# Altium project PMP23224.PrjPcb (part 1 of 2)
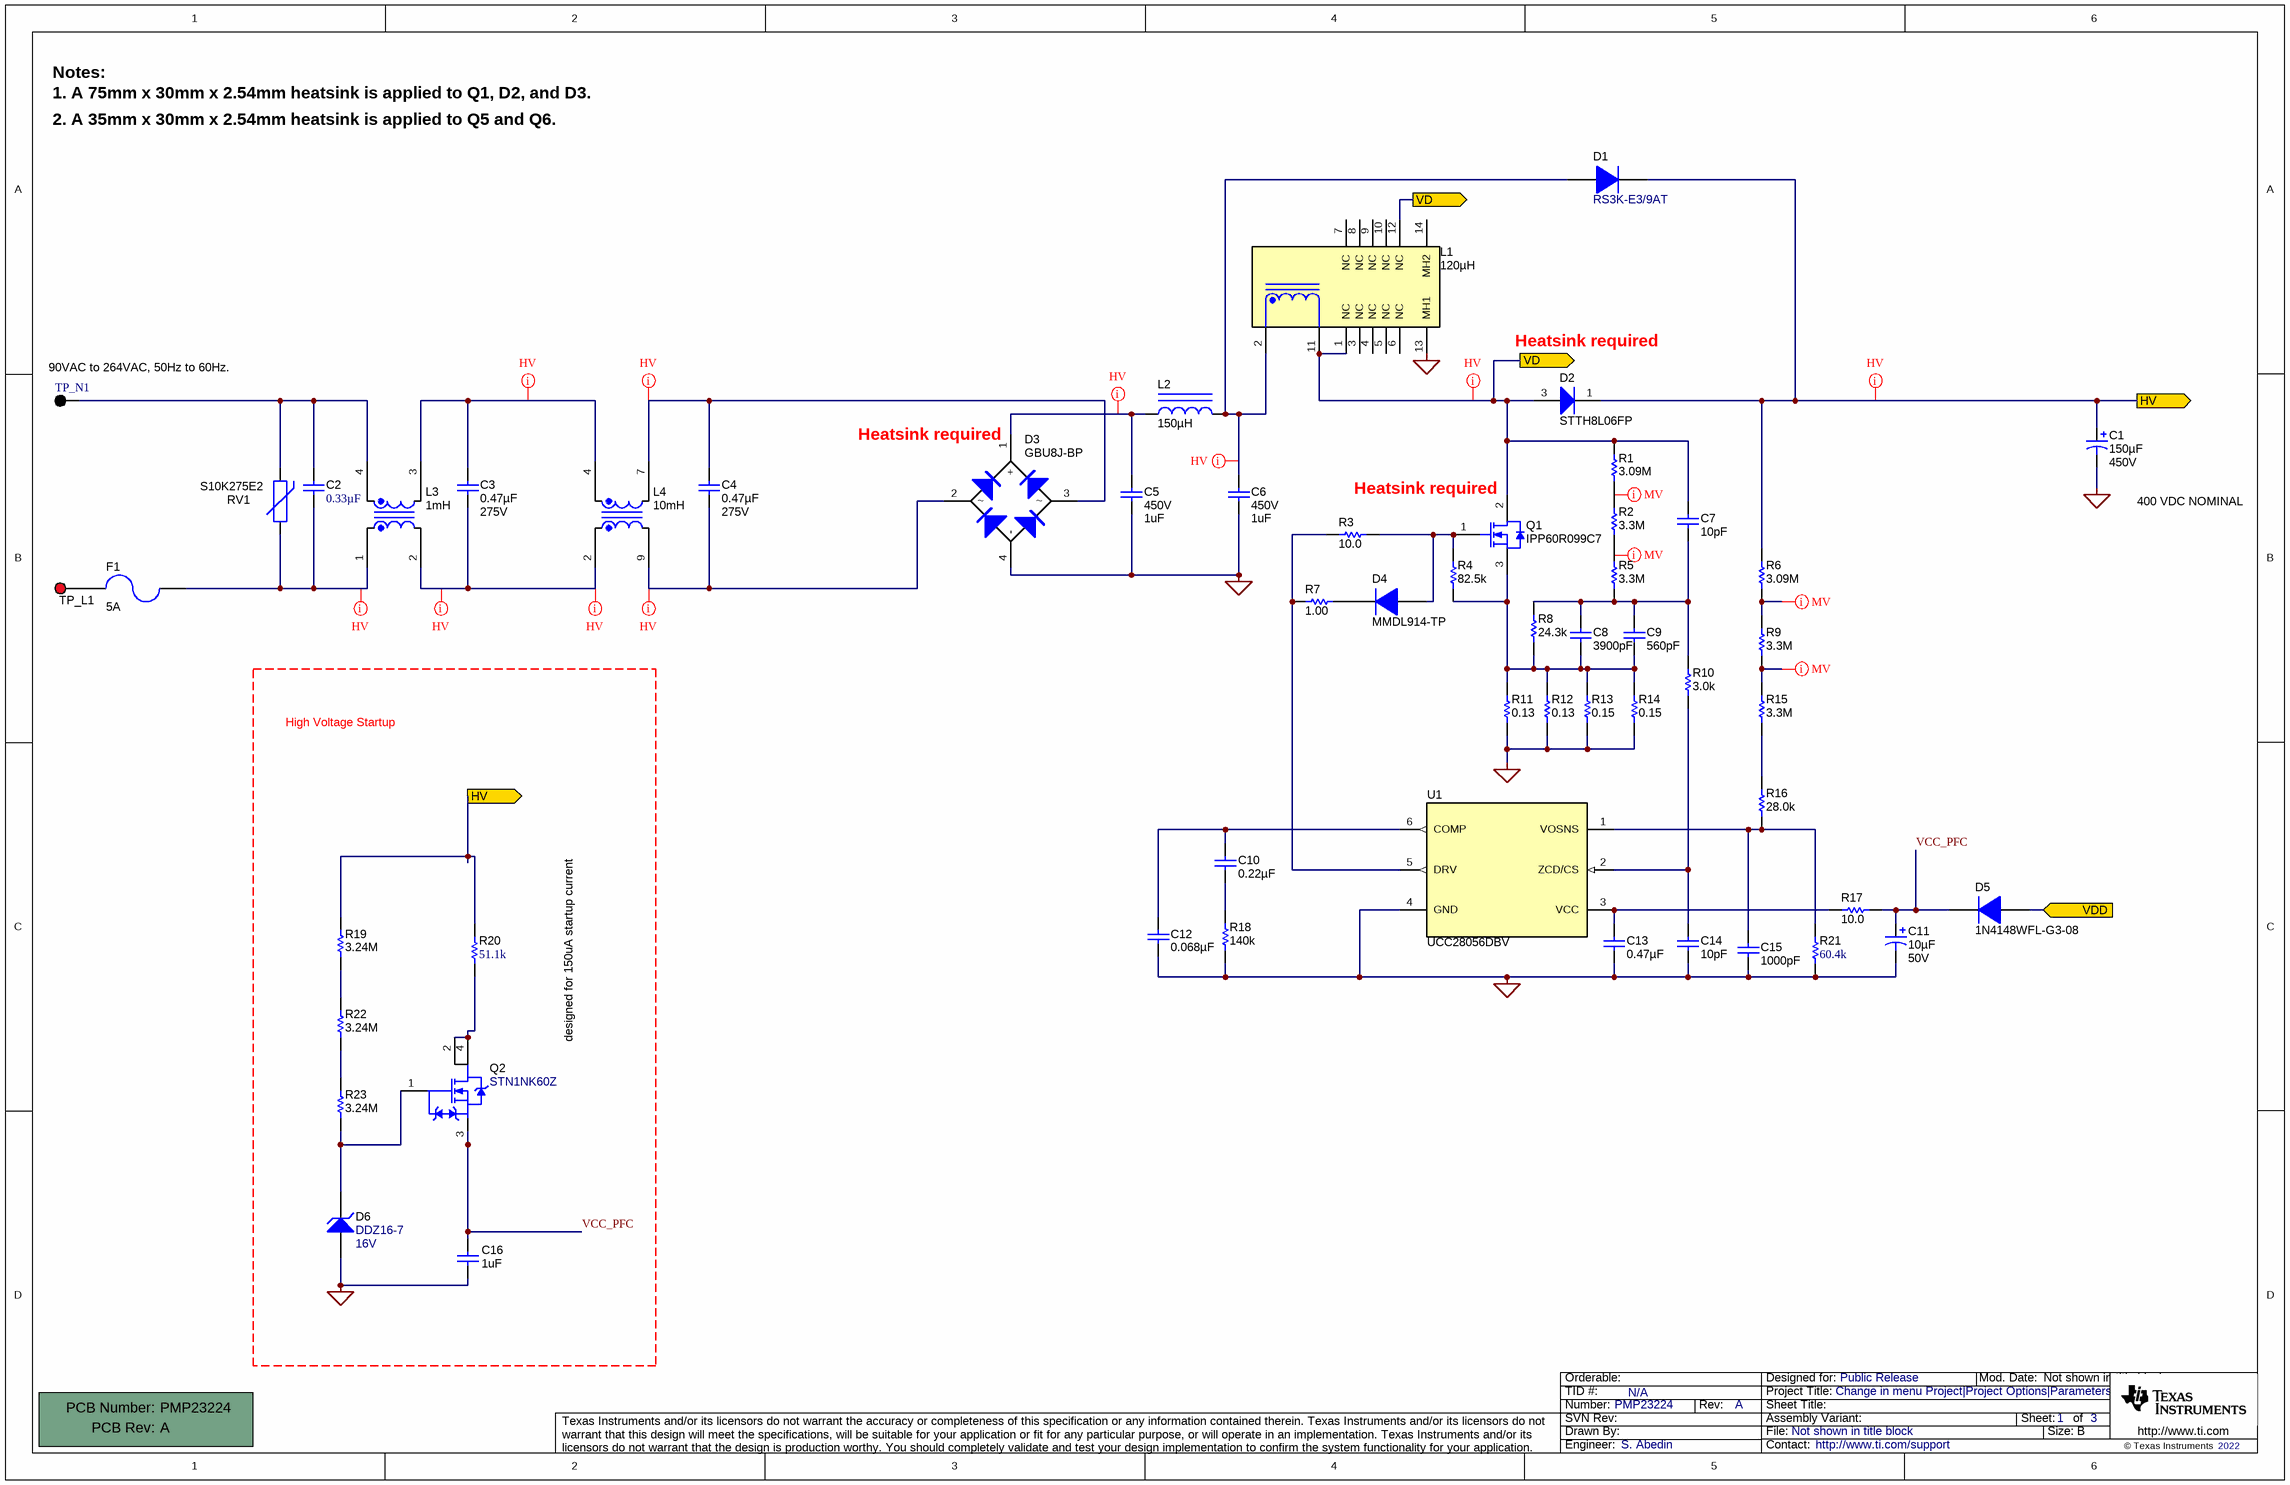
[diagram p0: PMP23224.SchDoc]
CopyrightYear: 2022; PCB_Layout: S. Abedin; PCB_Rev: A; PRJ_Customer: Public Release; PRJ_Engineer: S. Abedin; PRJ_Number: PMP23224; PRJ_Title: Change in menu Project|Project Options|Parameters; SCH_Rev: A; TechSupport: http://www.ti.com/support; TID: N/A
3 sheets, 191 parts. Net scope: flat (ports and power ports of the same name join across sheets).
Board file: PMP23224.PcbDoc
Sheets:
  PMP23224.SchDoc
  PMP23224_BlankSheet.SchDoc
  PMP23224_ACF_secondary.SchDoc

## Sheet PMP23224.SchDoc
size 431 x 279 mm; Date: Not shown in title block; ApprovedBy: Not shown in title block; CheckedBy: Not shown in title block; Author: Not shown in title block; CompanyName: Not shown in title block; Engineer: Not shown in title block; Organization: Not shown in title block; Address1: Not shown in title block; Address2: Not shown in title block; Address3: Not shown in title block; Address4: Not shown in title block; DocumentNumber: 1; Revision: Use project parameter SCH_Rev; SheetNumber: 1; SheetTotal: 3; PageSetup: Record=PageOptions¦CenterHorizontal=True¦CenterVertical=True¦PrintScale=1.00¦XCorrection=1.00¦YCorrection=1.00¦PrintKind=0¦BorderSize=5000000¦LeftOffset=0¦BottomOffset=0¦Orientation=2¦PaperLength=1000¦PaperWidth=1000¦Scale=100¦PaperSource=15¦PrintQuality=600¦MediaType=1¦DitherType=10¦PaperKind=Letter¦PrintScaleMode=1

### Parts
!PCB1  Printed Circuit Board  (value not drawn)  (mechanical)
C1  ValueDisplayed: 150µF  Value2: 450V  [SMQ_2540x2500]  (hidden comment: 450MXK150MEFCSN25X25)
C2  ValueDisplayed: 0.33µF  [WCAP-FTX2_1500x850]  (hidden comment: 890324024003)
C3  ValueDisplayed: 0.47µF  VAC_X: 275V  [WCAP-FTX2_1500x1000x1600]  (hidden comment: 890324024005)
C4  ValueDisplayed: 0.47µF  VAC_X: 275V  [WCAP-FTX2_1500x1000x1600]  (hidden comment: 890324024005)
C5  VDC_V: 450V  ValueDisplayed: 1uF  [MPK_1800x950]  (hidden comment: 450MPK105J)
C6  VDC_V: 450V  ValueDisplayed: 1uF  [MPK_1800x950]  (hidden comment: 450MPK105J)
C7  ValueDisplayed: 10pF  [1206]  (hidden comment: VJ1206A100JXGAT5Z)
C8  ValueDisplayed: 3900pF  [0603]  (hidden comment: GRM188R71E392KA01D)
C9  ValueDisplayed: 560pF  [0603]  (hidden comment: 06035A561JAT2A)
C10  ValueDisplayed: 0.22µF  [0603]  (hidden comment: 885012206048)
C11  ValueDisplayed: 10µF  Value2: 50V  [NHG_500x1100]  (hidden comment: ECA-1HHG100)
C12  ValueDisplayed: 0.068µF  [0603]  (hidden comment: C1608X5R1H683K080AA)
C13  ValueDisplayed: 0.47µF  [1206_180]  (hidden comment: CGA5L2X7R1H474K160AA)
C14  ValueDisplayed: 10pF  [0603]  (hidden comment: 0603ZC100KAT2A)
C15  ValueDisplayed: 1000pF  [0603]  (hidden comment: 06031C102KAT2A)
C16  ValueDisplayed: 1uF  [0805_HV1]  (hidden comment: C0805C105K3RACTU)
D1  RS3K-E3/9AT  [SMC]
D2  STTH8L06FP  [TO-220AC]
D3  GBU8J-BP  [GBU]
D4  MMDL914-TP  [SOD-323]
D5  1N4148WFL-G3-08  [SOD-123FL]
D6  DDZ16-7  value 16V  [SOD-123]
F1  Irating_A: 5A  [FUSE_372]  (hidden comment: 37215000001)
L1  ValueDisplayed: 120µH  [750317259]  (hidden comment: 750317259)
L2  ValueDisplayed: 150µH  [IND_7447020]  (hidden comment: 7447018)
L3  ValueDisplayed: 1mH  [IND_WE-CMB-S]  (hidden comment: 744822301)
L4  ValueDisplayed: 10mH  [IND_WE-CMB_L]  (hidden comment: 744824310)
Q1  IPP60R099C7  [TO-220AB]
Q2  STN1NK60Z  [SOT-223]
R1  ValueDisplayed: 3.09M  [1206]  (hidden comment: CRCW12063M09FKEA)
R2  ValueDisplayed: 3.3M  [1206]  (hidden comment: CRCW12063M30JNEA)
R3  ValueDisplayed: 10.0  [0603]  (hidden comment: CRCW060310R0FKEA)
R4  ValueDisplayed: 82.5k  [0603]  (hidden comment: CRCW060382K5FKEA)
R5  ValueDisplayed: 3.3M  [1206]  (hidden comment: CRCW12063M30JNEA)
R6  ValueDisplayed: 3.09M  [1206]  (hidden comment: CRCW12063M09FKEA)
R7  ValueDisplayed: 1.00  [0603]  (hidden comment: CRCW06031R00FKEA)
R8  ValueDisplayed: 24.3k  [0603]  (hidden comment: CRCW060324K3FKEA)
R9  ValueDisplayed: 3.3M  [1206]  (hidden comment: CRCW12063M30JNEA)
R10  ValueDisplayed: 3.0k  [0603]  (hidden comment: CRCW06033K00JNEA)
R11  ValueDisplayed: 0.13  [1206]  (hidden comment: CSR1206FTR130)
R12  ValueDisplayed: 0.13  [1206]  (hidden comment: CSR1206FTR130)
R13  ValueDisplayed: 0.15  [1206]  (hidden comment: ERJ-8BSFR15V)
R14  ValueDisplayed: 0.15  [1206]  (hidden comment: ERJ-8BSFR15V)
R15  ValueDisplayed: 3.3M  [1206]  (hidden comment: CRCW12063M30JNEA)
R16  ValueDisplayed: 28.0k  [0603]  (hidden comment: CRCW060328K0FKEA)
R17  ValueDisplayed: 10.0  [0805_HV]  (hidden comment: CRCW080510R0FKEA)
R18  ValueDisplayed: 140k  [0603]  (hidden comment: CRCW0603140KFKEA)
R19  ValueDisplayed: 3.24M  [1206]  (hidden comment: CRCW12063M24FKEA)
R20  ValueDisplayed: 51.1k  [1206]  (hidden comment: CRCW120651K1FKEA)
R21  ValueDisplayed: 60.4k  [0603]  (hidden comment: CRCW060360K4FKEA)
R22  ValueDisplayed: 3.24M  [1206]  (hidden comment: CRCW12063M24FKEA)
R23  ValueDisplayed: 3.24M  [1206]  (hidden comment: CRCW12063M24FKEA)
RV1  S10K275E2  [VAR_S10K275E2]
TP_L1  5010  [Keystone5010]  (value not drawn)
TP_N1  TP_N100  [Keystone5011]  (value not drawn)
U1  UCC28056DBV  [DBV0006A_N]

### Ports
HV (out), VD (out), VDD (in)

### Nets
GND: C1.2(-) C5.2 C6.2 C11.2(-) C12.2 C13.2 C14.2 C15.2 C16.2 D3.4(-) D6.2(A) L1.13(MH1) R11.1 R12.1 R13.1 R14.1 R18.1 R21.1 U1.4(GND)
HV: C1.1(+) D1.1(K) D2.1(K) R6.2 R19.2 R20.2 ; port HV
VCC_PFC: C11.1(+) C16.1 D5.1(K) Q2.3(S) R17.2
VD: C7.1 D2.3(A) L1.1(NC) L1.11 L1.12(NC) Q1.2(D) R1.2 ; port VD
VDD: D5.2(A) ; port VDD
NetC2_1: C2.1 L3.4 RV1.2 TP_N1.1
NetC2_2: C2.2 F1.2 L3.1 RV1.1
NetC3_1: C3.1 L3.3 L4.4
NetC3_2: C3.2 L3.2 L4.2
NetC4_1: C4.1 D3.3 L4.7
NetC4_2: C4.2 D3.2 L4.9
NetC5_1: C5.1 D3.1(+) L2.1
NetC6_1: C6.1 D1.2(A) L1.2 L2.2
NetC7_2: C7.2 C8.1 C9.1 R5.1 R8.2 R10.1
NetC8_2: C8.2 C9.2 Q1.3(S) R4.1 R8.1 R11.2 R12.2 R13.2 R14.2
NetC10_1: C10.1 C12.1 U1.6(COMP)
NetC10_2: C10.2 R18.2
NetC13_1: C13.1 R17.1 U1.3(VCC)
NetC14_1: C14.1 R10.2 U1.2(ZCD/CS)
NetC15_1: C15.1 R16.1 R21.2 U1.1(VOSNS)
NetD4_1: D4.1(K) R7.2
NetD4_2: D4.2(A) Q1.1(G) R3.2 R4.2
NetD6_1: D6.1(K) Q2.1(G) R23.1
NetF1_1: F1.1 TP_L1.1
NetQ2_2: Q2.2(D) Q2.4(D) R20.1
NetR1_1: R1.1 R2.2
NetR2_1: R2.1 R5.2
NetR3_1: R3.1 R7.1 U1.5(DRV)
NetR6_1: R6.1 R9.2
NetR9_1: R9.1 R15.2
NetR15_1: R15.1 R16.2
NetR19_1: R19.1 R22.2
NetR22_1: R22.1 R23.2

Not connected (* = marked no-connect by the designer): L1 3(NC) 4(NC) 5(NC) 6(NC) 7(NC) 8(NC) 9(NC) 10(NC) 14(MH2)

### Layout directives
net class HV: HV, NetC2_2, NetC3_1, NetC3_2, NetC4_1, NetC4_2, NetC5_1, NetC6_1, VD
net class MV: (no net found under the mark), NetR1_1, NetR6_1, NetR9_1

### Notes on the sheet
- Notes:
- 1. A 75mm x 30mm x 2.54mm heatsink is applied to Q1, D2, and D3.
- 2. A 35mm x 30mm x 2.54mm heatsink is applied to Q5 and Q6.
- (near TP_N1) 90VAC to 264VAC, 50Hz to 60Hz.
- (near D2) Heatsink required
- (near D3) Heatsink required
- Heatsink required
- 400 VDC NOMINAL
- High Voltage Startup
- designed for 150uA startup current

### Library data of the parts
!PCB1 = PCB: Manufacturer: Any; PartNumber: PMP23224; SymbolCreator: a0412235
C1 = ESMQ451VSN151MQ25S: CAP, AL, 150 µF, 450 V, +/- 20%, TH; Manufacturer: Rubycon; Polarized: Y; CompType: Capacitor; Value: 150uF; U/M: EA; Cap_F: 0.00015; Tolerance_%: 20; VDC_V: 450; IRMS_A: 1.19; TaMin_C: -25; TaMax_C: 85; Cap_Case: 25.4x25mm; SizeAreaWB_mm2: 750.76; SizeArea_mm2: 645.16; SizeX_mm: 25.4; SizeZ_mm: 27; AEC Category: Q200; AEC Qualified: N
C2 = CMP-0084596-1: CAP, Film, 0.33 µF, X2 275 VAC, +/- 10%, TH; Manufacturer: Wurth Elektronik; Cap_Case: 15x8.5mm; SizeAreaWB_mm2: 178.5; AEC Qualified: N; SizeX_mm: 15; Cap_F: 330nF; SizeY_mm: 8.5; VAC_X: 275; TaMin_C: -40°C; SizeZ_mm: 14.5; SizeArea_mm2: 127.5; Value: 0.33uF; TaMax_C: 105°C; AEC Category: Q200
C3 C4 = 890324024005: CAP, Film, 0.47 µF, X2 275 VAC, +/- 10%, TH; Manufacturer: Wurth Elektronik; Polarized: N; CompType: Capacitor; Value: 0.47uF; U/M: EA; Cap_F: 0.00000047; Tolerance_%: 10; TaMin_C: -40; TaMax_C: 105; Cap_Case: 15x10x16mm; SizeAreaWB_mm2: 204; SizeArea_mm2: 150; SizeX_mm: 15; SizeZ_mm: 16.5; AEC Category: Q200; Green_Lifecycle: Not Set; Green_REACh: Incomplete
C5 C6 = CMP-0012307-3: CAP, Film, 1 uF, 450 V, +/- 5%, TH; Manufacturer: Rubycon; TaMin_C: -40°C; Polarized: N; Value1: Unknown; Value: 1uF; TaMax_C: 105°C; Cap_Case: 18x9.5mm; CompType: Capacitor; Cap_F: 1µF; AEC Category: Q200
C7 = VJ1206A100JXGAT5Z: CAP, CERM, 10 pF, 1000 V,+/- 5%, C0G/NP0, 1206; Manufacturer: Vishay-Vitramon; Polarized: N; CompType: Capacitor; Value: 10pF; U/M: EA; Cap_F: 0.00000000001; Tolerance_%: 5; VDC_V: 1000; Value2: 1000V; TaMin_C: -55; TaMax_C: 125; SizeArea_mm2: 5.12; SizeAreaWB_mm2: 10.92; SizeX_mm: 3.2; SizeY_mm: 1.6; SizeZ_mm: 1.35; AEC Category: Q200
C8 = GRM188R71E392KA01D: CAP, CERM, 3900 pF, 25 V,+/- 10%, X7R, 0603; Manufacturer: MuRata; Polarized: N; CompType: Capacitor; Value: 3900pF; U/M: EA; Cap_F: 0.0000000039; Tolerance_%: 10; VDC_V: 25; Value2: 25V; TaMin_C: -55; TaMax_C: 125; SizeArea_mm2: 1.28; SizeAreaWB_mm2: 4.68; SizeX_mm: 1.6; SizeY_mm: 0.8; SizeZ_mm: 1; AEC Category: Q200; Green_Lifecycle: Active; Green_REACh: Passed
C9 = 06035A561JAT2A: CAP, CERM, 560 pF, 50 V,+/- 5%, C0G/NP0, 0603; Manufacturer: AVX; Polarized: N; CompType: Capacitor; Value: 560pF; U/M: EA; Cap_F: 0.00000000056; Tolerance_%: 5; ESR_ohm: 0.059; Value1: 0.059 ohm; VDC_V: 50; Value2: 50V; TaMin_C: -55; TaMax_C: 125; SizeArea_mm2: 1.28; SizeAreaWB_mm2: 4.68; SizeX_mm: 1.6; SizeY_mm: 0.8; SizeZ_mm: 1; AEC Category: Q200; Green_Lifecycle: Active; Green_REACh: Passed
C10 = 885012206048: CAP, CERM, 0.22 µF, 16 V,+/- 10%, X7R, 0603; Manufacturer: Wurth Elektronik; Polarized: N; CompType: Capacitor; Value: 0.22uF; U/M: EA; Cap_F: 0.00000022; Tolerance_%: 10; VDC_V: 16; Value2: 16V; TaMin_C: -55; TaMax_C: 125; SizeArea_mm2: 1.28; SizeAreaWB_mm2: 4.68; SizeX_mm: 1.6; SizeY_mm: 0.8; SizeZ_mm: 1; AEC Category: Q200
C11 = ECA-1HHG100: CAP, AL, 10 µF, 50 V, +/- 20%, TH; Manufacturer: Panasonic; Polarized: Y; CompType: Capacitor; Value: 10uF; U/M: EA; Cap_F: 0.00001; Tolerance_%: 20; VDC_V: 50; IRMS_A: 0.039; TaMin_C: -55; TaMax_C: 105; Cap_Case: 5x11mm; SizeAreaWB_mm2: 49; SizeArea_mm2: 25; SizeX_mm: 5; SizeZ_mm: 12; AEC Category: Q200; AEC Qualified: N
C12 = C1608X5R1H683K080AA: CAP, CERM, 0.068 µF, 50 V,+/- 10%, X5R, 0603; Manufacturer: TDK; Polarized: N; CompType: Capacitor; Value: 0.068uF; U/M: EA; Cap_F: 0.000000068; Tolerance_%: 10; ESR_ohm: 0.035979; Value1: 0.035979 ohm; VDC_V: 50; Value2: 50V; IRMS_A: 0.886483; TaMin_C: -55; TaMax_C: 85; SizeArea_mm2: 1.28; SizeAreaWB_mm2: 4.68; SizeX_mm: 1.6; SizeY_mm: 0.8; SizeZ_mm: 1; AEC Category: Q200; Green_Lifecycle: NRND; Green_REACh: Passed
C13 = CGA5L2X7R1H474K160AA: CAP, CERM, 0.47 µF, 50 V,+/- 10%, X7R, AEC-Q200 Grade 1, 1206; Manufacturer: TDK; Polarized: N; CompType: Capacitor; Value: 0.47uF; U/M: EA; Cap_F: 0.00000047; Tolerance_%: 10; ESR_ohm: 0.009426; Value1: 0.009426 ohm; VDC_V: 50; Value2: 50V; IRMS_A: 2.37046; TaMin_C: -55; TaMax_C: 125; Cap_Case: 1206; SizeArea_mm2: 5.12; SizeAreaWB_mm2: 10.92; SizeX_mm: 3.2; SizeY_mm: 1.6; SizeZ_mm: 1.8; AEC Category: Q200; AEC Qualified: Y; AEC Grade: 1
C14 = 0603ZC100KAT2A: CAP, CERM, 10 pF, 10 V,+/- 10%, X7R, 0603; Manufacturer: AVX; Polarized: N; CompType: Capacitor; Value: 10pF; U/M: EA; Cap_F: 0.00000000001; Tolerance_%: 10; Value1: Unknown; Value2: 10V; TaMin_C: -55; TaMax_C: 125; SizeArea_mm2: 1.28; SizeAreaWB_mm2: 4.68; SizeX_mm: 1.6; SizeY_mm: 0.8; SizeZ_mm: 1; AEC Category: Q200
C15 = 06031C102KAT2A: CAP, CERM, 1000 pF, 100 V,+/- 10%, X7R, 0603; Manufacturer: AVX; Polarized: N; CompType: Capacitor; Value: 1000pF; U/M: EA; Cap_F: 0.000000001; Tolerance_%: 10; ESR_ohm: 0.276; Value1: 0.276 ohm; VDC_V: 100; Value2: 100V; TaMin_C: -55; TaMax_C: 125; SizeArea_mm2: 1.28; SizeAreaWB_mm2: 4.68; SizeX_mm: 1.6; SizeY_mm: 0.8; SizeZ_mm: 1; AEC Category: Q200; Green_Lifecycle: Active; Green_REACh: Passed
C16 = CMP-0007728-2: CAP, CERM, 1 uF, 25 V, +/- 10%, X7R, 0805; Manufacturer: Kemet; Polarized: N; Value: 1uF; U/M: EA; Cap_F: 1µF; Value1: Unknown; VDC_V: 25V; TaMin_C: -55°C; TaMax_C: 125°C; Cap_Case: 0805; SizeArea_mm2: 2.5; SizeAreaWB_mm2: 6.75; SizeX_mm: 2; SizeY_mm: 1.25; SizeZ_mm: 1.45; AEC Category: Q200
D1 = CMP-0076883-2: Diode, Switching, 800 V, 3 A, SMC; Manufacturer: Vishay-Semiconductor; Vf_V: 1.3V; Value: 800V; Value1: 3A; TJmax_C: 150°C; RJC_CperW: 50.0; SizeAreaWB_mm2: 83.2686; SizeArea_mm2: 50.5686; SizeX_mm: 8.13; SizeY_mm: 6.22; SizeZ_mm: 2.6; AEC Category: Q101; Green_Lifecycle: Not Set; Green_REACh: Incomplete
D2 = STTH506DTI: DIODE GEN PURP 600V 8A TO220FP; Manufacturer: STMicroelectronics; SymbolCreator: a0412235; U/M: EA; Io_A: 5; Vr_V: 600; TJmax_C: 150; RJC_CperW: 3; Type: Ultrafast; SizeAreaWB_mm2: 78.975; SizeArea_mm2: 45.675; SizeX_mm: 10.15; SizeY_mm: 4.5; SizeZ_mm: 23; AEC Category: Q101; AEC Qualified: N; Green_Lifecycle: Not Set; Green_REACh: Incomplete
D3 = CMP-0029222-2: Diode, Switching-Bridge, 420 V, 8 A, TH; Manufacturer: Micro Commercial Components; Io_A: 8A; Green_Lifecycle: Not Set; SizeAreaWB_mm2: 130.5915; Vr_V: 420V; Green_REACh: Incomplete; TJmax_C: 175°C; U/M: EA; Value: 420V; SizeZ_mm: 21.55; SizeX_mm: 22.05; SizeY_mm: 3.43; Vf_V: 1V; SizeArea_mm2: 75.6315; AEC Category: Q101
D4 = MMDL914-TP: Diode, Switching, 100 V, 0.2 A, SOD-323; Manufacturer: Micro Commercial Components; U/M: EA; Vf_V: 1; Value: 100V; Value1: 0.2A; Value2: 1V; Io_A: 0.2; Vr_V: 100; TJmax_C: 150; SizeAreaWB_mm2: 8.695; SizeArea_mm2: 3.645; SizeX_mm: 2.7; SizeY_mm: 1.35; AEC Category: Q101
D5 = 1N4148WFL-G3-08: Diode, Switching, 100 V, 0.15 A, SOD-123FL; Manufacturer: Vishay-Semiconductor; U/M: EA; Vf_V: 1.2; Value: 100V; Value1: 0.15A; Value2: 1.2V; Io_A: 0.15; Vr_V: 100; TJmax_C: 150; SizeAreaWB_mm2: 12.19; SizeArea_mm2: 5.94; SizeX_mm: 3.6; SizeY_mm: 1.65; SizeZ_mm: 0.98; AEC Category: Q101; Green_Lifecycle: Not Set; Green_REACh: Incomplete
D6 = CMP-0085137-1: Diode, Zener, 16 V, 500 mW, SOD-123; Manufacturer: Diodes Inc.; AEC Category: Q101; SizeY_mm: 1.7; SizeX_mm: 3.85; Power_W: 500mW; SizeZ_mm: 1.35; SizeArea_mm2: 6.545; RJA_CperW: 425; AEC Qualified: N; SizeAreaWB_mm2: 13.095; Value1: 0.5W
F1 = 37215000001: Fuse, 5 A, 250VAC/VDC, TH; Manufacturer: Littelfuse; VDC_V: 250; MeltingTyp: 94
L1 = CMP-0078769-1: Inductor, 120 µH, 4 A, 0.055 ohm, TH; Manufacturer: Wurth Elektronik; SizeAreaWB_mm2: 1139.0625; SizeArea_mm2: 1008.0625; AEC Qualified: N; AEC Category: Q200; Value: 120uH; SizeZ_mm: 24.64; Imax_A: 4A; SizeY_mm: 31.75; Isat: 4A @ 20% inductance drop; DCR_ohm: 0.055
L2 = 7447020: 150µH Unshielded Toroidal Inductor 2A 80 mOhm Max Radial; Manufacturer: Wurth Elektronik; Ind_H: 100.0E-6; Imax_A: 1; Irms: 2.5A @ 40C rise; DCR_ohm: 0.16; Value1: 0.16 ohm; Material: Powdered Iron; SizeAreaWB_mm2: 169.1; SizeArea_mm2: 118.5; SizeX_mm: 7.5; SizeY_mm: 15.8; AEC Category: Q200
L3 = 744822301: Coupled inductor, 1 mH, 3 A, 0.035 ohm, TH; Manufacturer: Wurth Elektronik; SymbolCreator: a0412235; Value: 1mH; Ind_H: 1.0E-3; DCR_ohm: 0.035; AEC Category: Q200
L4 = 744824310: Coupled inductor, 10 mH, 3 A, 0.105 ohm, TH; Manufacturer: Wurth Elektronik; SymbolCreator: a0799628; Value: 10mH; Ind_H: 10.0E-3; DCR_ohm: 0.105; AEC Category: Q200
Q1 = IPP60R099C7XKSA1: MOSFET, N-CH, 600 V, 22 A, TO-220AB; Manufacturer: Infineon Technologies; Alternate Manufacturer: None; U/M: EA; ChType: N; Value: 600V; VdsMax_V: 600; Value1: ? ohm; Value2: 42 nC; QgTyp_nC: 42; Vgs_V: 30; IdsMax_A: 22; SizeAreaWB_mm2: 79.3; SizeArea_mm2: 45.9; SizeX_mm: 10.2; SizeY_mm: 4.5; SizeZ_mm: 19.4; AEC Category: Q101
Q2 = CMP-0001204-2: MOSFET, N-CH, 600 V, 0.3 A, SOT-223; Manufacturer: STMicroelectronics; Alternate Manufacturer: None; U/M: EA; ChType: N; Value: 600V; Value2: 4.9 nC; QgTyp_nC: 4.9; Vgs_V: 30V; IdsMax_A: 300mA; SizeAreaWB_mm2: 76.5; SizeArea_mm2: 45.5; SizeX_mm: 6.5; SizeY_mm: 7; SizeZ_mm: 1.6; AEC Category: Q101; AccessRights: 2147483647; ContentType: Component; Folder: Unified Components\Transistors\MOSFET\N-Channel\VDS 200 V+\; RevisionId: 1
R1 R6 = CRCW12063M09FKEA: RES, 3.09 M, 1%, 0.25 W, 1206; Manufacturer: Vishay-Dale; CompType: Resistor; Value: 3.09Meg; Res_ohm: 3090000; Value_Code: 3M09; Tolerance_%: 1; Power_W: 0.25; Value2: 0.25W; VDC_V: 200; TempCo: 100 ppm/C; SizeArea_mm2: 5.12; SizeX_mm: 3.2; SizeY_mm: 1.6; SizeZ_mm: 1.35; EIA_Code: E96; U/M: EA; AEC Category: Q200; Green_Lifecycle: Active; Green_REACh: Passed
R2 R5 R9 R15 = CRCW12063M30JNEA: RES, 3.3 M, 5%, 0.25 W, 1206; Manufacturer: Vishay-Dale; CompType: Resistor; Value: 3.3Meg; Res_ohm: 3300000; Value_Code: 3M30; Tolerance_%: 5; Power_W: 0.25; Value2: 0.25W; VDC_V: 200; TempCo: 200 ppm/C; SizeArea_mm2: 5.12; SizeX_mm: 3.2; SizeY_mm: 1.6; SizeZ_mm: 1.35; EIA_Code: E24; U/M: EA; AEC Category: Q200
R3 = CRCW060310R0FKEA: RES, 10.0, 1%, 0.1 W, 0603; Manufacturer: Vishay-Dale; CompType: Resistor; Value: 10.0; Res_ohm: 10; Value_Code: 10R0; Tolerance_%: 1; Power_W: 0.1; Value2: 0.1W; VDC_V: 75; TempCo: 100 ppm/C; SizeArea_mm2: 1.28; SizeX_mm: 1.6; SizeY_mm: 0.8; EIA_Code: E96; U/M: EA; AEC Category: Q200; Green_Lifecycle: Active; Green_REACh: Passed
R4 = CRCW060382K5FKEA: RES, 82.5 k, 1%, 0.1 W, 0603; Manufacturer: Vishay-Dale; CompType: Resistor; Value: 82.5k; Res_ohm: 82500; Value_Code: 82k5; Tolerance_%: 1; Power_W: 0.1; Value2: 0.1W; VDC_V: 75; TempCo: 100 ppm/C; SizeArea_mm2: 1.28; SizeX_mm: 1.6; SizeY_mm: 0.8; EIA_Code: E96; U/M: EA; AEC Category: Q200; Green_Lifecycle: Active; Green_REACh: Passed
R7 = CRCW06031R00FKEA: RES, 1.00, 1%, 0.1 W, 0603; Manufacturer: Vishay-Dale; CompType: Resistor; Value: 1.00; Res_ohm: 1; Value_Code: 1R00; Power_W: 0.1; Value2: 0.1W; VDC_V: 75; TempCo: 100 ppm/C; SizeArea_mm2: 1.28; SizeX_mm: 1.6; SizeY_mm: 0.8; EIA_Code: E96; U/M: EA; AEC Category: Q200; Green_Lifecycle: Active; Green_REACh: Passed
R8 = CRCW060324K3FKEA: RES, 24.3 k, 1%, 0.1 W, 0603; Manufacturer: Vishay-Dale; CompType: Resistor; Value: 24.3k; Res_ohm: 24300; Value_Code: 24k3; Tolerance_%: 1; Power_W: 0.1; Value2: 0.1W; VDC_V: 75; TempCo: 100 ppm/C; SizeArea_mm2: 1.28; SizeX_mm: 1.6; SizeY_mm: 0.8; EIA_Code: E96; U/M: EA; AEC Category: Q200; Green_Lifecycle: Active; Green_REACh: Passed
R10 = CRCW06033K00JNEA: RES, 3.0 k, 5%, 0.1 W, 0603; Manufacturer: Vishay-Dale; CompType: Resistor; Value: 3.0k; Res_ohm: 3000; Value_Code: 3k00; Tolerance_%: 5; Power_W: 0.1; Value2: 0.1W; VDC_V: 75; TempCo: 200 ppm/C; SizeArea_mm2: 1.28; SizeX_mm: 1.6; SizeY_mm: 0.8; SizeZ_mm: 1; EIA_Code: E24; U/M: EA; AEC Category: Q200; Green_Lifecycle: Active; Green_REACh: Passed
R11 R12 = CSR1206FTR130: RES, 0.13, 1%, 0.5 W, 1206; Manufacturer: Stackpole Electronics Inc; CompType: Resistor; Value: 0.13; Value_Code: R130; Tolerance_%: 1; Power_W: 0.5; Value2: 0.5W; TempCo: 100 ppm/C; SizeArea_mm2: 5.12; SizeX_mm: 3.2; SizeY_mm: 1.6; SizeZ_mm: 1.35; EIA_Code: E96; U/M: EA; AEC Category: Q200
R13 R14 = ERJ-8BSFR15V: RES, 0.15, 1%, 0.5 W, 1206; Manufacturer: Panasonic; CompType: Resistor; Value: 0.15; Value_Code: R150; Tolerance_%: 1; Power_W: 0.5; Value2: 0.5W; TempCo: 250 ppm/C; SizeArea_mm2: 5.12; SizeX_mm: 3.2; SizeY_mm: 1.6; SizeZ_mm: 1.35; EIA_Code: E96; U/M: EA; AEC Category: Q200; AEC Qualified: N
R16 = CMP-0022260-1: RES, 28.0 k, 1%, 0.1 W, 0603; Manufacturer: Vishay-Dale; Power_W: 100mW; TempCo: 100 ppm/C; Value_Code: 28k0; U/M: EA; Value: 28.0k; EIA_Code: E96; Res_ohm: 28k; SizeX_mm: 1.6; SizeY_mm: 0.8; SizeZ_mm: 1; Value2: 0.1W; SizeArea_mm2: 1.28; VDC_V: 75V; AEC Category: Q200
R17 = CRCW080510R0FKEA: RES, 10.0, 1%, 0.125 W, 0805; Manufacturer: Vishay-Dale; CompType: Resistor; Value: 10.0; Res_ohm: 10; Value_Code: 10R0; Tolerance_%: 1; Power_W: 0.125; Value2: 0.125W; VDC_V: 150; TempCo: 100 ppm/C; SizeArea_mm2: 2.5; SizeX_mm: 2; SizeY_mm: 1.25; SizeZ_mm: 1.45; EIA_Code: E96; U/M: EA; AEC Category: Q200; Green_Lifecycle: Active; Green_REACh: Passed
R18 = CRCW0603140KFKEA: RES, 140 k, 1%, 0.1 W, 0603; Manufacturer: Vishay-Dale; CompType: Resistor; Value: 140k; Res_ohm: 140000; Tolerance_%: 1; Power_W: 0.1; Value2: 0.1W; VDC_V: 75; TempCo: 100 ppm/C; SizeArea_mm2: 1.28; SizeX_mm: 1.6; SizeY_mm: 0.8; EIA_Code: E96; U/M: EA; AEC Category: Q200; Green_Lifecycle: Active; Green_REACh: Passed
R19 R22 R23 = CMP-0016959-3: RES, 3.24 M, 1%, 0.25 W, AEC-Q200 Grade 0, 1206; Manufacturer: Vishay-Dale; Value: 3.24Meg; Value_Code: 3M24; Power_W: 250mW; Value2: 0.25W; VDC_V: 200V; TempCo: 100 ppm/C; SizeArea_mm2: 5.12; SizeX_mm: 3.2; SizeY_mm: 1.6; SizeZ_mm: 1.35; EIA_Code: E96; AEC Category: Q200; AEC Qualified: Y; AEC Grade: 0
R20 = CMP-0017052-1: RES, 51.1 k, 1%, 0.25 W, 1206; Manufacturer: Vishay-Dale; Power_W: 250mW; TempCo: 100 ppm/C; Value_Code: 51k1; U/M: EA; Value: 51.1k; EIA_Code: E96; SizeX_mm: 3.2; SizeY_mm: 1.6; SizeZ_mm: 1.35; Value2: 0.25W; SizeArea_mm2: 5.12; VDC_V: 200V; AEC Category: Q200
R21 = CMP-0022532-2: RES, 60.4 k, 1%, 0.1 W, 0603; Manufacturer: Vishay-Dale; Power_W: 100mW; TempCo: 100 ppm/C; Value_Code: 60k4; U/M: EA; Value: 60.4k; EIA_Code: E96; SizeX_mm: 1.6; SizeY_mm: 0.8; SizeZ_mm: 1; Value2: 0.1W; SizeArea_mm2: 1.28; VDC_V: 75V; AEC Category: Q200
RV1 = S10K275E2: Varistor 275V RMS 10MM Radial, TH; Manufacturer: EPCOS Inc; SymbolCreator: a0412235
TP_L1 = 5010: Test Point, Multipurpose, Red, TH; Manufacturer: Keystone; CompType: Test Point Loop; ContactFinish: Silver
TP_N1 = CMP-0055148-2: Test Point, Multipurpose, Black, TH; Manufacturer: Keystone Electronics; CNHeader: FALSE; ContactFinish: Silver; Green_REACh: Passed; Green_Lifecycle: Active; CT: TRUE
U1 = UCC28056DBV: 6-Pin Single-Phase Transition-Mode PFC Controller, DBV0006A (SOT-23-6); Manufacturer: Texas Instruments; SymbolCreator: Altium; SizeArea_mm2: 8.12; SizeAreaWB_mm2: 14.82; SizeX_mm: 2.8; SizeY_mm: 2.9; SizeZ_mm: 1.45; CompType: IC; U/M: EA

## Sheet PMP23224_BlankSheet.SchDoc
size 431 x 279 mm; Date: Not shown in title block; ApprovedBy: Not shown in title block; CheckedBy: Not shown in title block; Author: Not shown in title block; CompanyName: Not shown in title block; Engineer: Not shown in title block; Organization: Not shown in title block; Address1: Not shown in title block; Address2: Not shown in title block; Address3: Not shown in title block; Address4: Not shown in title block; DocumentNumber: 2; Revision: Use project parameter SCH_Rev; SheetNumber: 2; SheetTotal: 3; PageSetup: Record=PageOptions¦CenterHorizontal=True¦CenterVertical=True¦PrintScale=1.00¦XCorrection=1.00¦YCorrection=1.00¦PrintKind=0¦BorderSize=5000000¦LeftOffset=0¦BottomOffset=0¦Orientation=2¦PaperLength=1000¦PaperWidth=1000¦Scale=100¦PaperSource=15¦PrintQuality=600¦MediaType=1¦DitherType=10¦PaperKind=Letter¦PrintScaleMode=1
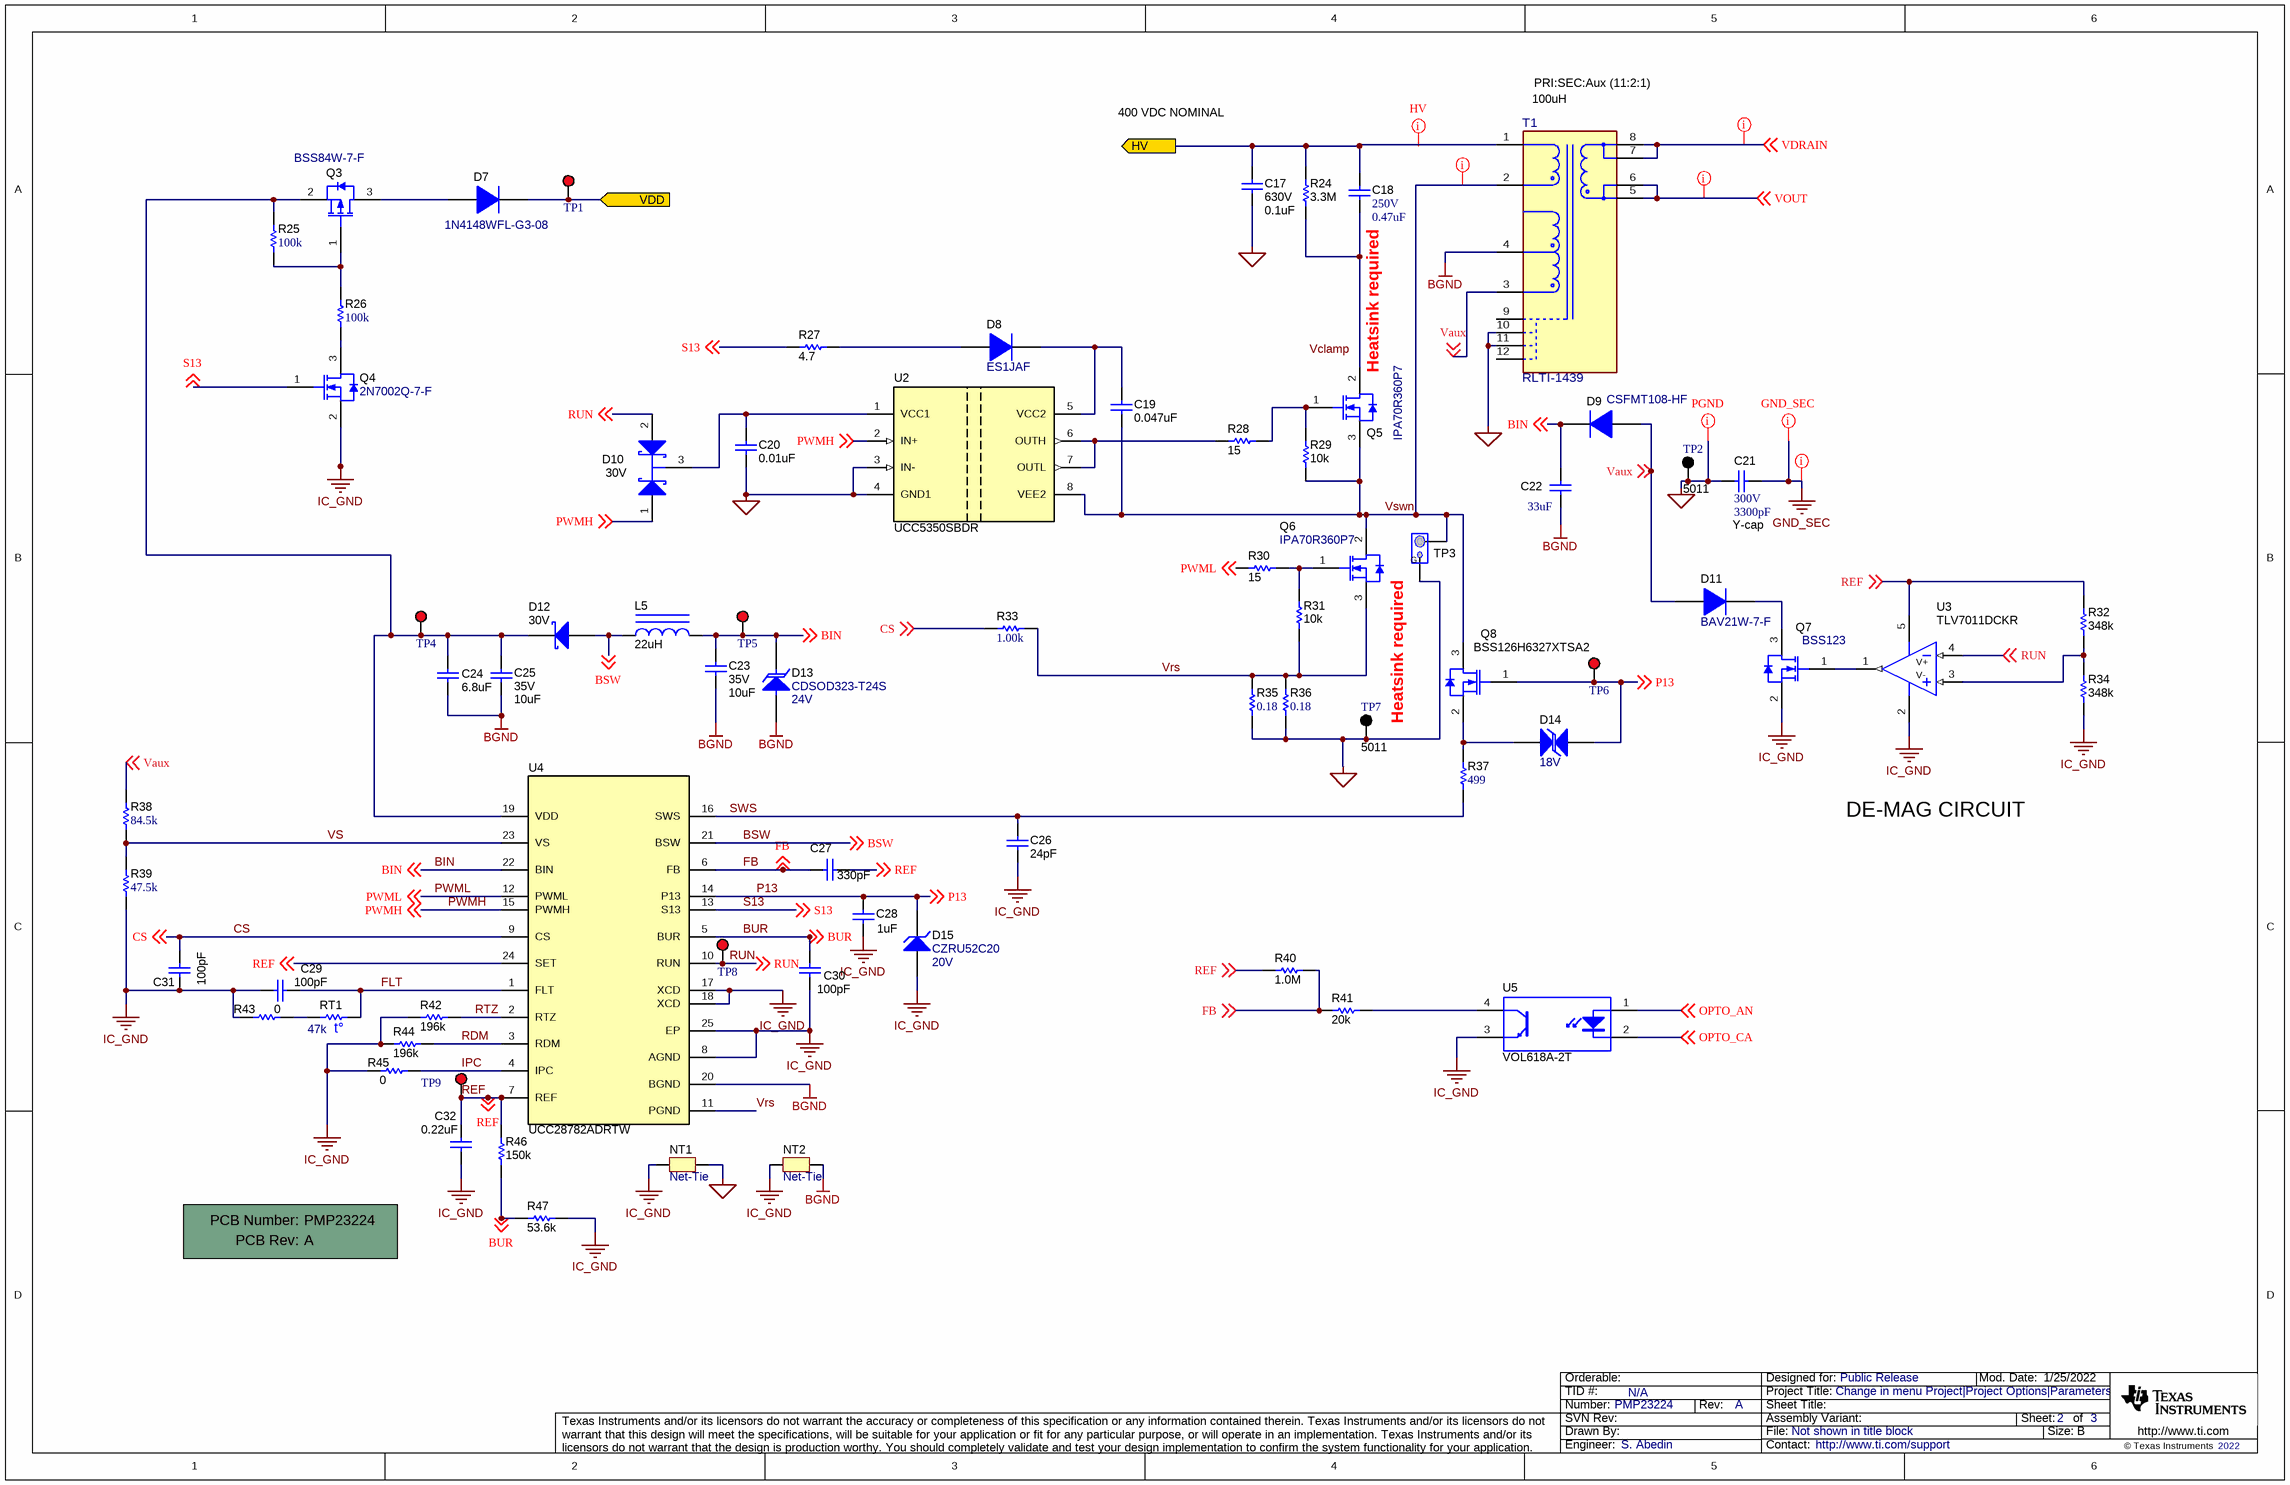
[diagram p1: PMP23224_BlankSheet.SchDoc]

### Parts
!PCB2  Printed Circuit Board  (value not drawn)  (mechanical)
C17  VDC_V: 630V  ValueDisplayed: 0.1uF  [1210_280]  (hidden comment: C1210C104KBRAC7800)
C18  VDC_V: 250V  ValueDisplayed: 0.47uF  [CAPRR1000W60L1300T600H1200]  (hidden comment: B32521C3474K)
C19  ValueDisplayed: 0.047uF  [0402S]  (hidden comment: GRM155R71E473KA88D)
C20  ValueDisplayed: 0.01uF  [0402S]  (hidden comment: GRM155R71E103KA01D)
C21  VDC_V: 300V  ValueDisplayed: 3300pF  [KX_1000x700]  (hidden comment: DE1E3KX332MN4AP01F)
C22  ValueDisplayed: 33uF  [1206_180]  (hidden comment: C3216X5R1E336M160AC)
C23  VDC_V: 35V  ValueDisplayed: 10uF  [0603S]  (hidden comment: GRM188R6YA106MA73)
C24  ValueDisplayed: 6.8uF  [0603S]  (hidden comment: C1608X5R1E685K080AC)
C25  VDC_V: 35V  ValueDisplayed: 10uF  [0603S]  (hidden comment: GRM188R6YA106MA73)
C26  ValueDisplayed: 24pF  [0402S]  (hidden comment: GRM1555C1H240JA01D)
C27  ValueDisplayed: 330pF  [0402S]  (hidden comment: GRM155R71H331KA01D)
C28  ValueDisplayed: 1uF  [0402S]  (hidden comment: GRM155R61E105KA12D)
C29  ValueDisplayed: 100pF  [0402S]  (hidden comment: GRM1555C1H101JA01D)
C30  ValueDisplayed: 100pF  [0402S]  (hidden comment: GRM1555C1H101JA01D)
C31  ValueDisplayed: 100pF  [0402S]  (hidden comment: GRM1555C1H101JA01D)
C32  ValueDisplayed: 0.22uF  [0402S]  (hidden comment: GRM155R71C224KA12D)
D7  1N4148WFL-G3-08  [SOD-123FL]
D8  ES1JAF  [SMAF]
D9  CSFMT108-HF  [SOD-123H]
D10  value 30V  [SOT-523]  (hidden comment: BAT54CT-7-F)
D11  BAV21W-7-F  [SOD-123]
D12  value 30V  [SOD-323]  (hidden comment: CUS08F30,H3F)
D13  CDSOD323-T24S  value 24V  [SOD-323]
D14  value 18V  [SOD-323-Bi]  (hidden comment: CDSOD323-T18C)
D15  CZRU52C20  value 20V  [SOD-523F]
L5  ValueDisplayed: 22uH  [1007]  (hidden comment: BRC2518T220K)
NT1  Net-Tie  [Net-Tie_10mil]  (net tie, no BOM)
NT2  Net-Tie  [Net-Tie_10mil]  (net tie, no BOM)
Q3  BSS84W-7-F  [SOT-323]
Q4  2N7002Q-7-F  [SOT-23]
Q5  IPA70R360P7  [TO-220-3]
Q6  IPA70R360P7  [TO-220-3]
Q7  BSS123  [SOT-23]
Q8  BSS126H6327XTSA2  [SOT-23]
R24  ValueDisplayed: 3.3M  [1206L]  (hidden comment: CRCW12063M30JNEA)
R25  ValueDisplayed: 100k  [0402S]  (hidden comment: CRCW0402100KFKED)
R26  ValueDisplayed: 100k  [0402S]  (hidden comment: CRCW0402100KFKED)
R27  ValueDisplayed: 4.7  [0402S]  (hidden comment: CRCW04024R70JNED)
R28  ValueDisplayed: 15  [0402S]  (hidden comment: CRCW040215R0JNED)
R29  ValueDisplayed: 10k  [0402S]  (hidden comment: CRCW040210K0JNED)
R30  ValueDisplayed: 15  [0402S]  (hidden comment: CRCW040215R0JNED)
R31  ValueDisplayed: 10k  [0402S]  (hidden comment: CRCW040210K0JNED)
R32  ValueDisplayed: 348k  [0402S]  (hidden comment: CRCW0402348KFKED)
R33  ValueDisplayed: 1.00k  [0402]  (hidden comment: CRCW04021K00FKED)
R34  ValueDisplayed: 348k  [0402S]  (hidden comment: CRCW0402348KFKED)
R35  ValueDisplayed: 0.18  [1210]  (hidden comment: ERJ14RSJR18U)
R36  ValueDisplayed: 0.18  [1210]  (hidden comment: ERJ14RSJR18U)
R37  ValueDisplayed: 499  [0402S]  (hidden comment: CRCW0402499RFKED)
R38  ValueDisplayed: 84.5k  [0805_HV]  (hidden comment: CRCW080584K5FKEA)
R39  ValueDisplayed: 47.5k  [0402]  (hidden comment: CRCW040247K5FKED)
R40  ValueDisplayed: 1.0M  [0402S]  (hidden comment: CRCW04021M00JNED)
R41  ValueDisplayed: 20k  [0402S]  (hidden comment: CRCW040220K0JNED)
R42  ValueDisplayed: 196k  [0402S]  (hidden comment: CRCW0402196KFKED)
R43  ValueDisplayed: 0  [0402S]  (hidden comment: CRCW04020000Z0ED)
R44  ValueDisplayed: 196k  [0402S]  (hidden comment: CRCW0402196KFKED)
R45  ValueDisplayed: 0  [0402S]  (hidden comment: CRCW04020000Z0ED)
R46  ValueDisplayed: 150k  [0402S]  (hidden comment: CRCW0402150KFKED)
R47  ValueDisplayed: 53.6k  [0402S]  (hidden comment: CRCW040253K6FKED)
RT1  value 47k  [0603S]  (hidden comment: NCP18WB473J03RB)
T1  RLTI-1439  [FP-RLTI-1439_PTH_XFRMR_2IN20_1IN73-MFG]
TP1  5010  [Keystone5010]  (value not drawn)
TP2  5011  [Keystone5011]
TP3  TESTPOINT_PIGTAIL  [TESTPOINT_PIGTAIL]  (value not drawn)  (no BOM)
TP4  5010  [Keystone5010]  (value not drawn)
TP5  5010  [Keystone5010]  (value not drawn)
TP6  5010  [Keystone5010]  (value not drawn)
TP7  5011  [Keystone5011]
TP8  5010  [Keystone5010]  (value not drawn)
TP9  5010  [Keystone5010]  (value not drawn)
U2  UCC5350SBDR  [D0008B_L]
U3  TLV7011DCKR  [DCK0005A_N]
U4  UCC28782ADRTW  [RTW0024B]
U5  VOL618A-2T  [SOP254P1020X230-4]

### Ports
HV (out), VDD (in)

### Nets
BGND: C22.2 C23.2 C24.2 C25.2 D13.2(A) NT2.2 T1.4(PGND) U4.20(BGND)
GND: C17.2 C20.2 C21.2 NT1.2 R35.1 R36.1 T1.10(PGND) T1.11(PGND) TP2.1 TP3.2 TP7.1 U2.3(IN-) U2.4(GND1)
GND_SEC: C21.1
IC_GND: C26.2 C28.2 C29.2 C30.2 C31.1 C32.2 D15.2(A) NT1.1 NT2.1 Q4.2(S) Q7.2(S) R34.2 R39.1 R42.1 R43.1 R44.1 R45.2 R47.2 U3.2(V-) U4.8(AGND) U4.17(XCD) U4.18(XCD) U4.25(EP) U5.3(E)
BIN: C22.1 C23.1 D9.1(K) D13.1(K) L5.2 TP5.1 U4.22(BIN) ; off-sheet BIN
BSW: D12.2(A) L5.1 U4.21(BSW) ; off-sheet BSW
BUR: C30.1 R46.1 R47.1 U4.5(BUR) ; off-sheet BUR
CS: C31.2 R33.1 U4.9(CS) ; off-sheet CS
FB: C27.1 R40.1 R41.1 U4.6(FB) ; off-sheet FB
FLT: C29.1 RT1.2 U4.1(FLT)
HV: C17.1 C18.1 R24.2 T1.1(VBULK) ; port HV
IPC: R45.1 U4.4(IPC)
OPTO_AN: U5.1(A) ; off-sheet OPTO_AN
OPTO_CA: U5.2(K) ; off-sheet OPTO_CA
P13: C28.1 D14.1 D15.1(K) Q8.1(G) TP6.1 U4.14(P13) ; off-sheet P13
PWMH: D10.1(A1) U2.2(IN+) U4.15(PWMH) ; off-sheet PWMH
PWML: R30.1 U4.12(PWML) ; off-sheet PWML
RDM: R44.2 U4.3(RDM)
REF: C27.2 C32.1 R32.2 R40.2 R46.2 TP9.1 U3.5(V+) U4.7(REF) U4.24(SET) ; off-sheet REF
RTZ: R42.2 U4.2(RTZ)
RUN: D10.2(A2) TP8.1 U3.4(IN-) U4.10(RUN) ; off-sheet RUN
S13: Q4.1(G) R27.1 U4.13(S13) ; off-sheet S13
SWS: C26.1 R37.1 U4.16(SWS)
Vaux: D9.2(A) D11.2(A) R38.2 T1.3(15V) ; off-sheet Vaux
VDD: D7.1(K) TP1.1 ; port VDD
VDRAIN: T1.7(SR_FET) T1.8(SR_FET) ; off-sheet VDRAIN
VOUT: T1.5(6-22V) T1.6(6-22V) ; off-sheet VOUT
Vrs: Q6.3(S) R31.1 R33.2 R35.2 R36.2 U4.11(PGND)
VS: R38.1 R39.2 U4.23(VS)
Vswn: C19.2 Q5.3(S) Q6.2(D) Q8.3(D) R29.1 T1.2(VSWITCH) TP3.1 U2.8(VEE2)
NetC18_2: C18.2 Q5.2(D) R24.1
NetC19_1: C19.1 D8.1(K) U2.5(VCC2)
NetC20_1: C20.1 D10.3(K) U2.1(VCC1)
NetC24_1: C24.1 C25.1 D12.1(K) Q3.2(S) R25.2 TP4.1 U4.19(VDD)
NetD7_2: D7.2(A) Q3.3(D)
NetD8_2: D8.2(A) R27.2
NetD11_1: D11.1(K) Q7.3(D)
NetD14_2: D14.2 Q8.2(S) R37.2
NetQ3_1: Q3.1(G) R25.1 R26.2
NetQ4_3: Q4.3(D) R26.1
NetQ5_1: Q5.1(G) R28.2 R29.2
NetQ6_1: Q6.1(G) R30.2 R31.2
NetQ7_1: Q7.1(G) U3.1(OUT)
NetR28_1: R28.1 U2.6(OUTH) U2.7(OUTL)
NetR32_1: R32.1 R34.1 U3.3(IN+)
NetR41_2: R41.2 U5.4(C)
NetR43_2: R43.2 RT1.1

Not connected (* = marked no-connect by the designer): T1 9(PGND) 12(PGND)

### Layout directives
net class GND_SEC: GND_SEC
net class VDRN: VDRAIN
net class RTN: VOUT
net class HV: (no net found under the mark)
net class PGND: GND
net class GND_SEC; net class *: GND_SEC

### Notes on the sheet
- (near T1) 100uH
- PRI:SEC:Aux (11:2:1)
- 400 VDC NOMINAL
- Heatsink required
- (near C21) Y-cap
- DE-MAG CIRCUIT
- Labels drawn without touching a wire or pin: Vclamp

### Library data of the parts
!PCB2 = CMP-0003618-2: Manufacturer: Any; PartNumber: PMP23224
C17 = CMP-0009076-1: CAP, CERM, 0.1 uF, 630 V, +/- 10%, X7R, 1210; Manufacturer: Kemet; TaMin_C: -55°C; Polarized: N; SizeAreaWB_mm2: 14.7; Value1: Unknown; U/M: EA; Value: 0.1uF; TaMax_C: 125°C; SizeZ_mm: 2.8; SizeX_mm: 3.2; SizeY_mm: 2.5; Cap_Case: 1210; SizeArea_mm2: 8; Cap_F: 100nF; AEC Category: Q200
C18 = CMP-0012326-3: CAP, Film, 0.47 uF, 250 V, +/- 10%, TH; Manufacturer: TDK; TaMin_C: -55°C; Polarized: N; SizeAreaWB_mm2: 120; Value1: Unknown; Value: 0.47uF; TaMax_C: 125°C; SizeZ_mm: 12; SizeX_mm: 13; SizeY_mm: 6; Cap_Case: Radial 13x6x12mm; SizeArea_mm2: 78; Cap_F: 470nF; AEC Category: Q200
C19 = CMP-0006669-2: CAP, CERM, 0.047 uF, 25 V, +/- 10%, X7R, 0402; Manufacturer: MuRata; TaMin_C: -55°C; Polarized: N; SizeAreaWB_mm2: 3; Value1: Unknown; U/M: EA; TaMax_C: 125°C; SizeZ_mm: 0.6; SizeX_mm: 1; SizeY_mm: 0.5; Cap_Case: 0402; Value2: 25V; Cap_F: 47nF; AEC Category: Q200
C20 = CMP-0006658-2: CAP, CERM, 0.01 uF, 25 V, +/- 10%, X7R, 0402; Manufacturer: MuRata; TaMin_C: -55°C; Polarized: N; SizeAreaWB_mm2: 3; Value1: Unknown; U/M: EA; Value: 0.01uF; TaMax_C: 125°C; SizeZ_mm: 0.6; SizeX_mm: 1; SizeY_mm: 0.5; Cap_Case: 0402; Value2: 25V; CompType: Capacitor; Cap_F: 10nF; AEC Category: Q200
C21 = CMP-0009604-2: CAP, CERM, 3300 pF, 300 V, +/- 20%, E, D10xT7mm; Manufacturer: MuRata; TaMin_C: -40°C; Polarized: N; SizeAreaWB_mm2: 108; Value1: Unknown; U/M: EA; Value: 3300pF; TaMax_C: 125°C; SizeZ_mm: 13; SizeX_mm: 10; SizeY_mm: 7; Cap_Case: 10x7mm; SizeArea_mm2: 70; Cap_F: 3.3nF; AEC Category: Q200
C22 = CMP-0008655-2: CAP, CERM, 33 µF, 25 V, +/- 20%, X5R, 1206; Manufacturer: TDK; TaMin_C: -55°C; ESR_ohm: 2.648m; Polarized: N; SizeAreaWB_mm2: 10.92; Value1: 0.002648 ohm; U/M: EA; Value: 33uF; TaMax_C: 85°C; SizeZ_mm: 1.8; SizeX_mm: 3.2; SizeY_mm: 1.6; Value2: 25V; SizeArea_mm2: 5.12; CompType: Capacitor; Cap_F: 33µF; IRMS_A: 4.45864A; AEC Category: Q200
C23 C25 = CMP-0007355-3: CAP, CERM, 10 uF, 35 V, +/- 20%, X5R, 0603; Manufacturer: Nichicon; TaMin_C: -55°C; Polarized: N; SizeAreaWB_mm2: 4.68; Value1: Unknown; U/M: EA; Value: 10uF; TaMax_C: 85°C; SizeZ_mm: 1; SizeX_mm: 1.6; SizeY_mm: 0.8; Cap_Case: 0603; SizeArea_mm2: 1.28; Cap_F: 10µF; AEC Category: Q200
C24 = CMP-0007009-5: CAP, CERM, 6.8 µF, 25 V, +/- 10%, X5R, 0603; Manufacturer: TDK; TaMin_C: -55°C; ESR_ohm: 4.211m; Polarized: N; SizeAreaWB_mm2: 4.68; Value1: 0.004211 ohm; U/M: EA; Value: 6.8uF; TaMax_C: 85°C; SizeZ_mm: 1; SizeX_mm: 1.6; SizeY_mm: 0.8; Cap_Case: 0603; Value2: 25V; SizeArea_mm2: 1.28; Cap_F: 6.8µF; IRMS_A: 2.534067A; AEC Category: Q200
C26 = CMP-0006441-2: CAP, CERM, 24 pF, 50 V, +/- 5%, C0G/NP0, 0402; Manufacturer: MuRata; TaMin_C: -55°C; Polarized: N; SizeAreaWB_mm2: 3; Value1: Unknown; U/M: EA; Value: 24pF; TaMax_C: 125°C; SizeZ_mm: 0.6; SizeX_mm: 1; SizeY_mm: 0.5; Cap_Case: 0402; Value2: 50V; CompType: Capacitor; AEC Category: Q200
C27 = CMP-0006687-2: CAP, CERM, 330 pF, 50 V, +/- 10%, X7R, 0402; Manufacturer: MuRata; TaMin_C: -55°C; Polarized: N; SizeAreaWB_mm2: 3; Value1: Unknown; U/M: EA; Value: 330pF; TaMax_C: 125°C; SizeZ_mm: 0.6; SizeX_mm: 1; SizeY_mm: 0.5; Cap_Case: 0402; Value2: 50V; AEC Category: Q200
C28 = CMP-0006608-2: CAP, CERM, 1 µF, 25 V, +/- 10%, X5R, 0402; Manufacturer: MuRata; TaMin_C: -55°C; Polarized: N; SizeAreaWB_mm2: 3; Value1: Unknown; U/M: EA; Value: 1uF; TaMax_C: 85°C; SizeZ_mm: 0.6; SizeX_mm: 1; SizeY_mm: 0.5; Cap_Case: 0402; Value2: 25V; Cap_F: 1µF; AEC Category: Q200
C29 = CMP-0006410-2: CAP, CERM, 100 pF, 50 V, +/- 5%, C0G/NP0, 0402; Manufacturer: MuRata; TaMin_C: -55°C; Polarized: N; SizeAreaWB_mm2: 3; Value1: Unknown; U/M: EA; Value: 100pF; TaMax_C: 125°C; SizeZ_mm: 0.6; SizeX_mm: 1; SizeY_mm: 0.5; Cap_Case: 0402; Value2: 50V; AEC Category: Q200
C30 C31 = CMP-0006410-2: CAP, CERM, 100 pF, 50 V, +/- 5%, C0G/NP0, 0402; Manufacturer: MuRata; TaMin_C: -55°C; Polarized: N; SizeAreaWB_mm2: 3; Value1: Unknown; U/M: EA; Value: 100pF; TaMax_C: 125°C; SizeZ_mm: 0.6; SizeX_mm: 1; SizeY_mm: 0.5; Cap_Case: 0402; Value2: 50V; CompType: Capacitor; AEC Category: Q200
C32 = CMP-0006648-2: CAP, CERM, 0.22 µF, 16 V, +/- 10%, X7R, 0402; Manufacturer: MuRata; TaMin_C: -55°C; Polarized: N; SizeAreaWB_mm2: 3; Value1: Unknown; U/M: EA; Value: 0.22uF; TaMax_C: 125°C; SizeZ_mm: 0.6; SizeX_mm: 1; SizeY_mm: 0.5; Cap_Case: 0402; Value2: 16V; Cap_F: 220nF; AEC Category: Q200
D7 = CMP-0076920-2: Diode, Switching, 100 V, 0.15 A, SOD-123FL; Manufacturer: Vishay-Semiconductor; Vf_V: 1.2V; Value: 100V; Value1: 0.15A; Io_A: 150mA; TJmax_C: 150°C; SizeAreaWB_mm2: 12.19; SizeArea_mm2: 5.94; SizeX_mm: 3.6; SizeY_mm: 1.65; SizeZ_mm: 0.98; AEC Category: Q101; Green_Lifecycle: Not Set; Green_REACh: Incomplete
D8 = CMP-0029162-1: Diode, Ultrafast, 600 V, 1 A, AEC-Q101, SMAF; Manufacturer: Fairchild Semiconductor; Io_A: 1A; Green_Lifecycle: Not Set; SizeAreaWB_mm2: 19.95; Vr_V: 600V; Green_REACh: Incomplete; TJmax_C: 150°C; U/M: EA; Value: 600V; SizeZ_mm: 1; SizeX_mm: 4.7; SizeY_mm: 2.5; Vf_V: 1.7V; SizeArea_mm2: 11.75; AEC Qualified: Y; AEC Category: Q101
D9 = CMP-0077074-2: Diode, Superfast Rectifier, 600 V, 1 A, 3.5x1.6mm; Manufacturer: Comchip Technology; Vf_V: 1.7V; Value: 600V; Value1: 1A; TJmax_C: 150°C; AEC Category: Q101; AEC Qualified: N; Green_Lifecycle: Not Set; Green_REACh: Incomplete; SizeArea_mm2: 5.6; SizeAreaWB_mm2: 11.7; SizeX_mm: 3.5; SizeY_mm: 1.6; SizeZ_mm: 1.0
D10 = CMP-0028454-2: Diode, Schottky, 30 V, 0.2 A, SOT-523; Manufacturer: Diodes Inc.; AEC Category: Q101; Green_REACh: Incomplete; SizeAreaWB_mm2: 6.76; SizeY_mm: 1.6; SizeZ_mm: 0.8; Green_Lifecycle: Not Set; SizeArea_mm2: 2.56; TJmax_C: 125°C; Vf_V: 700mV; Value2: 0.7V; Io_A: 200mA; Value1: 0.2A
D11 = CMP-0029031-1: Diode, Switching, 200 V, 0.2 A, SOD-123; Manufacturer: Diodes Inc.; Io_A: 200mA; Green_Lifecycle: Active; SizeAreaWB_mm2: 13.095; Vr_V: 200V; Green_REACh: Passed; Value1: 0.2A; TJmax_C: 150°C; U/M: EA; Value: 200V; SizeZ_mm: 1.35; SizeX_mm: 3.85; SizeY_mm: 1.7; Vf_V: 1.25V; SizeArea_mm2: 6.545; AEC Category: Q101
D12 = CMP-0028882-2: Diode, Schottky, 30 V, 0.8 A, SOD-323; Manufacturer: Toshiba; Vf_V: 800mA; Value1: 0.8A; Io_A: 750mA; TJmax_C: 150°C; SizeAreaWB_mm2: 8.695; SizeArea_mm2: 3.645; SizeX_mm: 2.7; SizeY_mm: 1.35; SizeZ_mm: 1; AEC Category: Q101; AEC Qualified: Y; Green_Lifecycle: Not Set; Green_REACh: Incomplete
D13 = CMP-0005823-4: Diode, TVS, Uni, 24 V, 49 Vc, SOD-323; Manufacturer: Bourns; SizeY_mm: 1.35; SizeX_mm: 2.7; SizeZ_mm: 1; SizeArea_mm2: 3.645; AEC Category: Q101; Value1: 500W; AEC Qualified: N; SizeAreaWB_mm2: 8.695; Vbr_Min: 26.7V; Vc: 49V; Ipp: 12A
D14 = CMP-0005822-3: Diode, TVS, Bi, 18 V, SOD-323; Manufacturer: Bourns; SizeArea_mm2: 3.645; SizeY_mm: 1.35; VRWM: 24V; Ppk: 350W; SizeZ_mm: 1; SizeX_mm: 2.7; SizeAreaWB_mm2: 8.695; AEC Category: Q101
D15 = CMP-0005911-2: Diode, Zener, 20 V, 150 mW, SOD-523F; Manufacturer: Comchip Technology; Power_W: 150mW; SizeAreaWB_mm2: 5.13; Value1: 0.15W; U/M: EA; SizeZ_mm: 0.85; SizeX_mm: 1.7; SizeY_mm: 0.9; SizeArea_mm2: 1.53; AEC Qualified: N; AEC Category: Q101
L5 = CMP-0060002-1: Inductor, Wirewound, 22 uH, 0.49 A, 0.56 ohm, SMD; Manufacturer: Taiyo Yuden; Isat: 0.64A @ 30% inductance drop; Irms: 0.49A @ 40C rise; Green_Lifecycle: Active; SizeAreaWB_mm2: 9.8; DCR_ohm: 0.56; Green_REACh: Passed; Value: 22uH; Imax_A: 490mA; SizeZ_mm: 2; SizeX_mm: 2.5; SizeY_mm: 1.8; Value2: 0.49A; SizeArea_mm2: 4.5; Ind_H: 22µH; AEC Qualified: N; AEC Category: Q200
NT1 NT2 = CMP-0078142-1: Single point connection between nets.
Q3 = CMP-0000015-1: MOSFET, P-CH, -50 V, -0.13 A, SOT-323; Alternate Manufacturer: None; Manufacturer: Diodes Inc.; SizeZ_mm: 1.1; ChType: P; Value1: 1; VdsMax_V: -50V; SizeX_mm: 2.2; Vgs_V: -20V; Value: -50V; Rdson45_ohm: 10; SizeArea_mm2: 4.84; AEC Category: Q101; IdsMax_A: -130mA; SizeAreaWB_mm2: 10.24; U/M: EA
Q4 = CMP-0085603-1: MOSFET, N-CH, 60 V, 0.115 A, AEC-Q101, SOT-23; Manufacturer: Diodes Inc.; Alternate Manufacturer: None; SizeAreaWB_mm2: 14; Value: 60V; QgTyp_nC: 0.223; IdsMax_A: 115mA; AEC Category: Q101; SizeY_mm: 3; SizeArea_mm2: 7.5; SizeX_mm: 2.5; SizeZ_mm: 1.1; Value1: ? ohm; ChMode: Enhancement; Vgs_V: 20V; ChType: N; AEC Qualified: Y; Value2: 0.223 nC
Q5 Q6 = CMP-0084435-1: MOSFET, N-CH, 650 V, 9 A; Alternate Manufacturer: None; Manufacturer: Infineon Technologies; ChMode: Enhancement; SizeZ_mm: 20.68; Value: 700V; Value1: ? ohm; AEC Category: Q101; ChType: N; SizeX_mm: 8.47; SizeAreaWB_mm2: 127.3152; SizeArea_mm2: 86.0552; VdsMax_V: 700; Value2: 18 nC; QgTyp_nC: 18; SizeY_mm: 10.16; Vgs_V: 20V; IdsMax_A: 9A
Q7 = CMP-0000947-1: MOSFET, N-CH, 100 V, 0.17 A, SOT-23; Alternate Manufacturer: None; Manufacturer: Fairchild Semiconductor; SizeZ_mm: 1.1; ChType: N; Value2: 1.8 nC; Value1: 1; VdsMax_V: 100V; SizeX_mm: 2.5; SizeY_mm: 3; Vgs_V: 20V; Value: 100V; Rdson45_ohm: 10; SizeArea_mm2: 7.5; AEC Category: Q101; IdsMax_A: 170mA; SizeAreaWB_mm2: 14; U/M: EA; QgTyp_nC: 1.8
Q8 = CMP-0067574-2: MOSFET, N-CH, Depletion Mode, 100 V, 0.17 A, AEC-Q101, SOT-23; Manufacturer: Infineon Technologies; Alternate Manufacturer: None; ChType: N; Value: 600V; Value1: ? ohm; Value2: 1.4 nC; QgTyp_nC: 1.4; Vgs_V: 20V; IdsMax_A: 21mA; SizeAreaWB_mm2: 14.0; SizeArea_mm2: 7.5; SizeX_mm: 2.5; SizeY_mm: 3.0; SizeZ_mm: 1.1; AEC Category: Q101; AEC Qualified: Y
R24 = CMP-0018673-3: RES, 3.3 M, 5%, 0.25 W, AEC-Q200 Grade 0, 1206; Manufacturer: Vishay-Dale; CompType: Resistor; Value: 3.3Meg; Value_Code: 3M30; Power_W: 250mW; Value2: 0.25W; VDC_V: 200V; TempCo: 200 ppm/C; SizeArea_mm2: 5.12; SizeX_mm: 3.2; SizeY_mm: 1.6; SizeZ_mm: 1.35; EIA_Code: E24; AEC Category: Q200; AEC Qualified: Y; AEC Grade: 0
R25 R26 = CMP-0025950-1: RES, 100 k, 1%, 0.063 W, 0402; Manufacturer: Vishay-Dale; Power_W: 63mW; TempCo: 100 ppm/C; U/M: EA; Value: 100k; EIA_Code: E96; SizeX_mm: 1; SizeY_mm: 0.5; SizeZ_mm: 0.6; Value2: 0.063W; VDC_V: 50V; AEC Category: Q200
R27 = CMP-0026942-3: RES, 4.7, 5%, 0.063 W, AEC-Q200 Grade 0, 0402; Manufacturer: Vishay-Dale; Power_W: 63mW; TempCo: 200 ppm/C; Value_Code: 4R70; Value: 4.7; EIA_Code: E24; SizeX_mm: 1; SizeY_mm: 0.5; SizeZ_mm: 0.6; Value2: 0.063W; AEC Qualified: Y; VDC_V: 50V; AEC Category: Q200; AEC Grade: 0
R28 R30 = CMP-0026843-3: RES, 15, 5%, 0.063 W, AEC-Q200 Grade 0, 0402; Manufacturer: Vishay-Dale; Power_W: 63mW; TempCo: 200 ppm/C; Value_Code: 15R0; Value: 15; EIA_Code: E24; SizeX_mm: 1; SizeY_mm: 0.5; SizeZ_mm: 0.6; Value2: 0.063W; CompType: Resistor; AEC Qualified: Y; VDC_V: 50V; AEC Category: Q200; AEC Grade: 0
R29 R31 = CMP-0026825-5: RES, 10 k, 5%, 0.063 W, AEC-Q200 Grade 0, 0402; Manufacturer: Vishay-Dale; Power_W: 63mW; TempCo: 200 ppm/C; Value_Code: 10k0; Value: 10k; EIA_Code: E24; SizeX_mm: 1; SizeY_mm: 0.5; SizeZ_mm: 0.6; Value2: 0.063W; CompType: Resistor; AEC Qualified: Y; VDC_V: 50V; AEC Category: Q200; AEC Grade: 0
R32 R34 = CMP-0026302-1: RES, 348 k, 1%, 0.063 W, 0402; Manufacturer: Vishay-Dale; Power_W: 63mW; TempCo: 100 ppm/C; U/M: EA; Value: 348k; EIA_Code: E96; SizeX_mm: 1; SizeY_mm: 0.5; SizeZ_mm: 0.6; Value2: 0.063W; VDC_V: 50V; AEC Category: Q200
R33 = CMP-0026071-1: RES, 1.00 k, 1%, 0.063 W, 0402; Manufacturer: Vishay-Dale; Power_W: 63mW; TempCo: 100 ppm/C; Value_Code: 1k00; U/M: EA; Value: 1.00k; EIA_Code: E96; Res_ohm: 1k; SizeX_mm: 1; SizeY_mm: 0.5; SizeZ_mm: 0.6; Value2: 0.063W; VDC_V: 50V; AEC Category: Q200
R35 R36 = CMP-0015329-1: RES, 0.18, 5%, 0.25 W, 1210; Manufacturer: Panasonic; Power_W: 250mW; TempCo: 200 ppm/C; SizeAreaWB_mm2: 14.7; Value_Code: R180; U/M: EA; Value: 0.18; EIA_Code: E24; SizeX_mm: 3.2; SizeY_mm: 2.5; SizeZ_mm: 1.35; Value2: 0.25W; SizeArea_mm2: 8; AEC Category: Q200
R37 = CMP-0026402-2: RES, 499, 1%, 0.063 W, AEC-Q200 Grade 0, 0402; Manufacturer: Vishay-Dale; Power_W: 63mW; TempCo: 100 ppm/C; Value_Code: 499R; Value: 499; EIA_Code: E96; SizeX_mm: 1; SizeY_mm: 0.5; SizeZ_mm: 0.6; Value2: 0.063W; AEC Qualified: Y; VDC_V: 50V; AEC Category: Q200; AEC Grade: 0
R38 = CMP-0021459-2: RES, 84.5 k, 1%, 0.125 W, 0805; Manufacturer: Vishay-Dale; Power_W: 125mW; TempCo: 100 ppm/C; Value_Code: 84k5; U/M: EA; Value: 84.5k; EIA_Code: E96; SizeX_mm: 2; SizeY_mm: 1.25; SizeZ_mm: 1.45; Value2: 0.125W; SizeArea_mm2: 2.5; VDC_V: 150V; AEC Category: Q200
R39 = CMP-0026395-1: RES, 47.5 k, 1%, 0.063 W, 0402; Manufacturer: Vishay-Dale; Power_W: 63mW; TempCo: 100 ppm/C; Value_Code: 47k5; U/M: EA; Value: 47.5k; EIA_Code: E96; SizeX_mm: 1; SizeY_mm: 0.5; SizeZ_mm: 0.6; Value2: 0.063W; VDC_V: 50V; AEC Category: Q200
R40 = CMP-0026859-2: RES, 1.0 M, 5%, 0.063 W, AEC-Q200 Grade 0, 0402; Manufacturer: Vishay-Dale; CompType: Resistor; Value: 1.0Meg; Res_ohm: 1M; Value_Code: 1M00; Power_W: 63mW; Value2: 0.063W; VDC_V: 50V; TempCo: 200 ppm/C; SizeArea_mm2: 0.5; SizeX_mm: 1; SizeZ_mm: 0.6; EIA_Code: E24; AEC Category: Q200; AEC Qualified: Y; AEC Grade: 0
R41 = CMP-0026875-1: RES, 20 k, 5%, 0.063 W, 0402; Manufacturer: Vishay-Dale; Power_W: 63mW; TempCo: 200 ppm/C; Value_Code: 20k0; U/M: EA; Value: 20k; EIA_Code: E24; SizeX_mm: 1; SizeY_mm: 0.5; SizeZ_mm: 0.6; Value2: 0.063W; VDC_V: 50V; AEC Category: Q200
R42 R44 = CMP-0026065-1: RES, 196 k, 1%, 0.063 W, 0402; Manufacturer: Vishay-Dale; Power_W: 63mW; TempCo: 100 ppm/C; U/M: EA; Value: 196k; EIA_Code: E96; SizeX_mm: 1; SizeY_mm: 0.5; SizeZ_mm: 0.6; Value2: 0.063W; VDC_V: 50V; AEC Category: Q200
R43 R45 = CMP-0026822-3: RES, 0, 5%, 0.063 W, AEC-Q200 Grade 0, 0402; Manufacturer: Vishay-Dale; Power_W: 63mW; TempCo: 200 ppm/C; Value_Code: 0000; Value: 0; EIA_Code: E24; SizeX_mm: 1; SizeY_mm: 0.5; SizeZ_mm: 0.6; Value2: 0.063W; CompType: Resistor; AEC Qualified: Y; VDC_V: 50V; AEC Category: Q200
R46 = CMP-0026021-1: RES, 150 k, 1%, 0.063 W, 0402; Manufacturer: Vishay-Dale; Power_W: 63mW; TempCo: 100 ppm/C; U/M: EA; Value: 150k; EIA_Code: E96; SizeX_mm: 1; SizeY_mm: 0.5; SizeZ_mm: 0.6; Value2: 0.063W; VDC_V: 50V; AEC Category: Q200
R47 = CMP-0026445-1: RES, 53.6 k, 1%, 0.063 W, 0402; Manufacturer: Vishay-Dale; Power_W: 63mW; TempCo: 100 ppm/C; Value_Code: 53k6; U/M: EA; Value: 53.6k; EIA_Code: E96; SizeX_mm: 1; SizeY_mm: 0.5; SizeZ_mm: 0.6; Value2: 0.063W; VDC_V: 50V; AEC Category: Q200
RT1 = CMP-0002523-3: Thermistor NTC, 47k ohm, 5%, 0603; Manufacturer: MuRata; TaMax_C: 125°C; SizeX_mm: 1.6; SizeY_mm: 0.8; TaMin_C: -40°C; Power_W: 100mW; SizeZ_mm: 1; SizeArea_mm2: 1.28; SizeAreaWB_mm2: 4.68; U/M: EA
T1 = CMP-0095835-1: Flyback for PMP23224; Manufacturer: Renco Electronics; Ns1toNp: 1:0.454:0.181:0.181; AEC Qualified: No; Ind_H: 100µH; DCR_ohm: 55m; Rsec1_ohm: 3m; SizeZ_mm: 1.26inch; Voltage_Isolation_Vrms: 3kV
TP1 TP4-TP6 TP8 TP9 = CMP-0055147-1: Test Point, Multipurpose, Red, TH; Manufacturer: Keystone; ContactFinish: Silver; Green_Lifecycle: Active; Green_REACh: Passed; CNHeader: FALSE; CT: TRUE
TP2 TP7 = CMP-0055148-1: Test Point, Multipurpose, Black, TH; Manufacturer: Keystone; ContactFinish: Silver; Green_Lifecycle: Active; Green_REACh: Passed; CNHeader: FALSE; CT: TRUE
TP3 = CMP-0003907-1: PIGTAIL; Manufacturer: Texas Instruments
U2 = CMP-0077706-1: 3-kVRMS Single-Channel Isolated Gate Drivers, D0008B (SOIC-8); Alternate Manufacturer: Texas Instruments; SizeAreaWB_mm2: 55.2; SizeZ_mm: 1.75; SizeX_mm: 6.0; SizeY_mm: 4.9; SizeArea_mm2: 29.4; CompType: IC; AEC Qualified: N; AEC Category: Q200
U3 = CMP-0860894-1: Low power, small size comparator with push-pull output, DCK0005A (SOT-SC70-5); Alternate Manufacturer: Texas Instruments; Alternate PartNumber: TLV7011DCKT; CompType: IC; SizeZ_mm: 1.1; SizeY_mm: 2; AEC Qualified: N; AEC Category: Q200; SizeX_mm: 2.1; SizeAreaWB_mm2: 9.3; SizeArea_mm2: 4.2; Rating: Catalog
U4 = CMP-0086087-1: UCC28782ADRTW, RTW0024B (WQFN-24); Manufacturer: Texas Instruments; SizeY_mm: 4; SizeZ_mm: 0.8; AEC Category: Q200; SizeArea_mm2: 16; CompType: IC; AEC Qualified: N; SizeAreaWB_mm2: 25
U5 = CMP-0006160-3: Optocoupler, 5 kV, 63-125% CTR, SMT; Manufacturer: Vishay-Semiconductor; CTR (Max): 125%; SizeAreaWB_mm2: 74.42; CTR (Min): 63%; SizeZ_mm: 2.3; SizeX_mm: 10.2; SizeY_mm: 4.1; SizeArea_mm2: 41.82; Voltage_Isolation_Vrms: 5kV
